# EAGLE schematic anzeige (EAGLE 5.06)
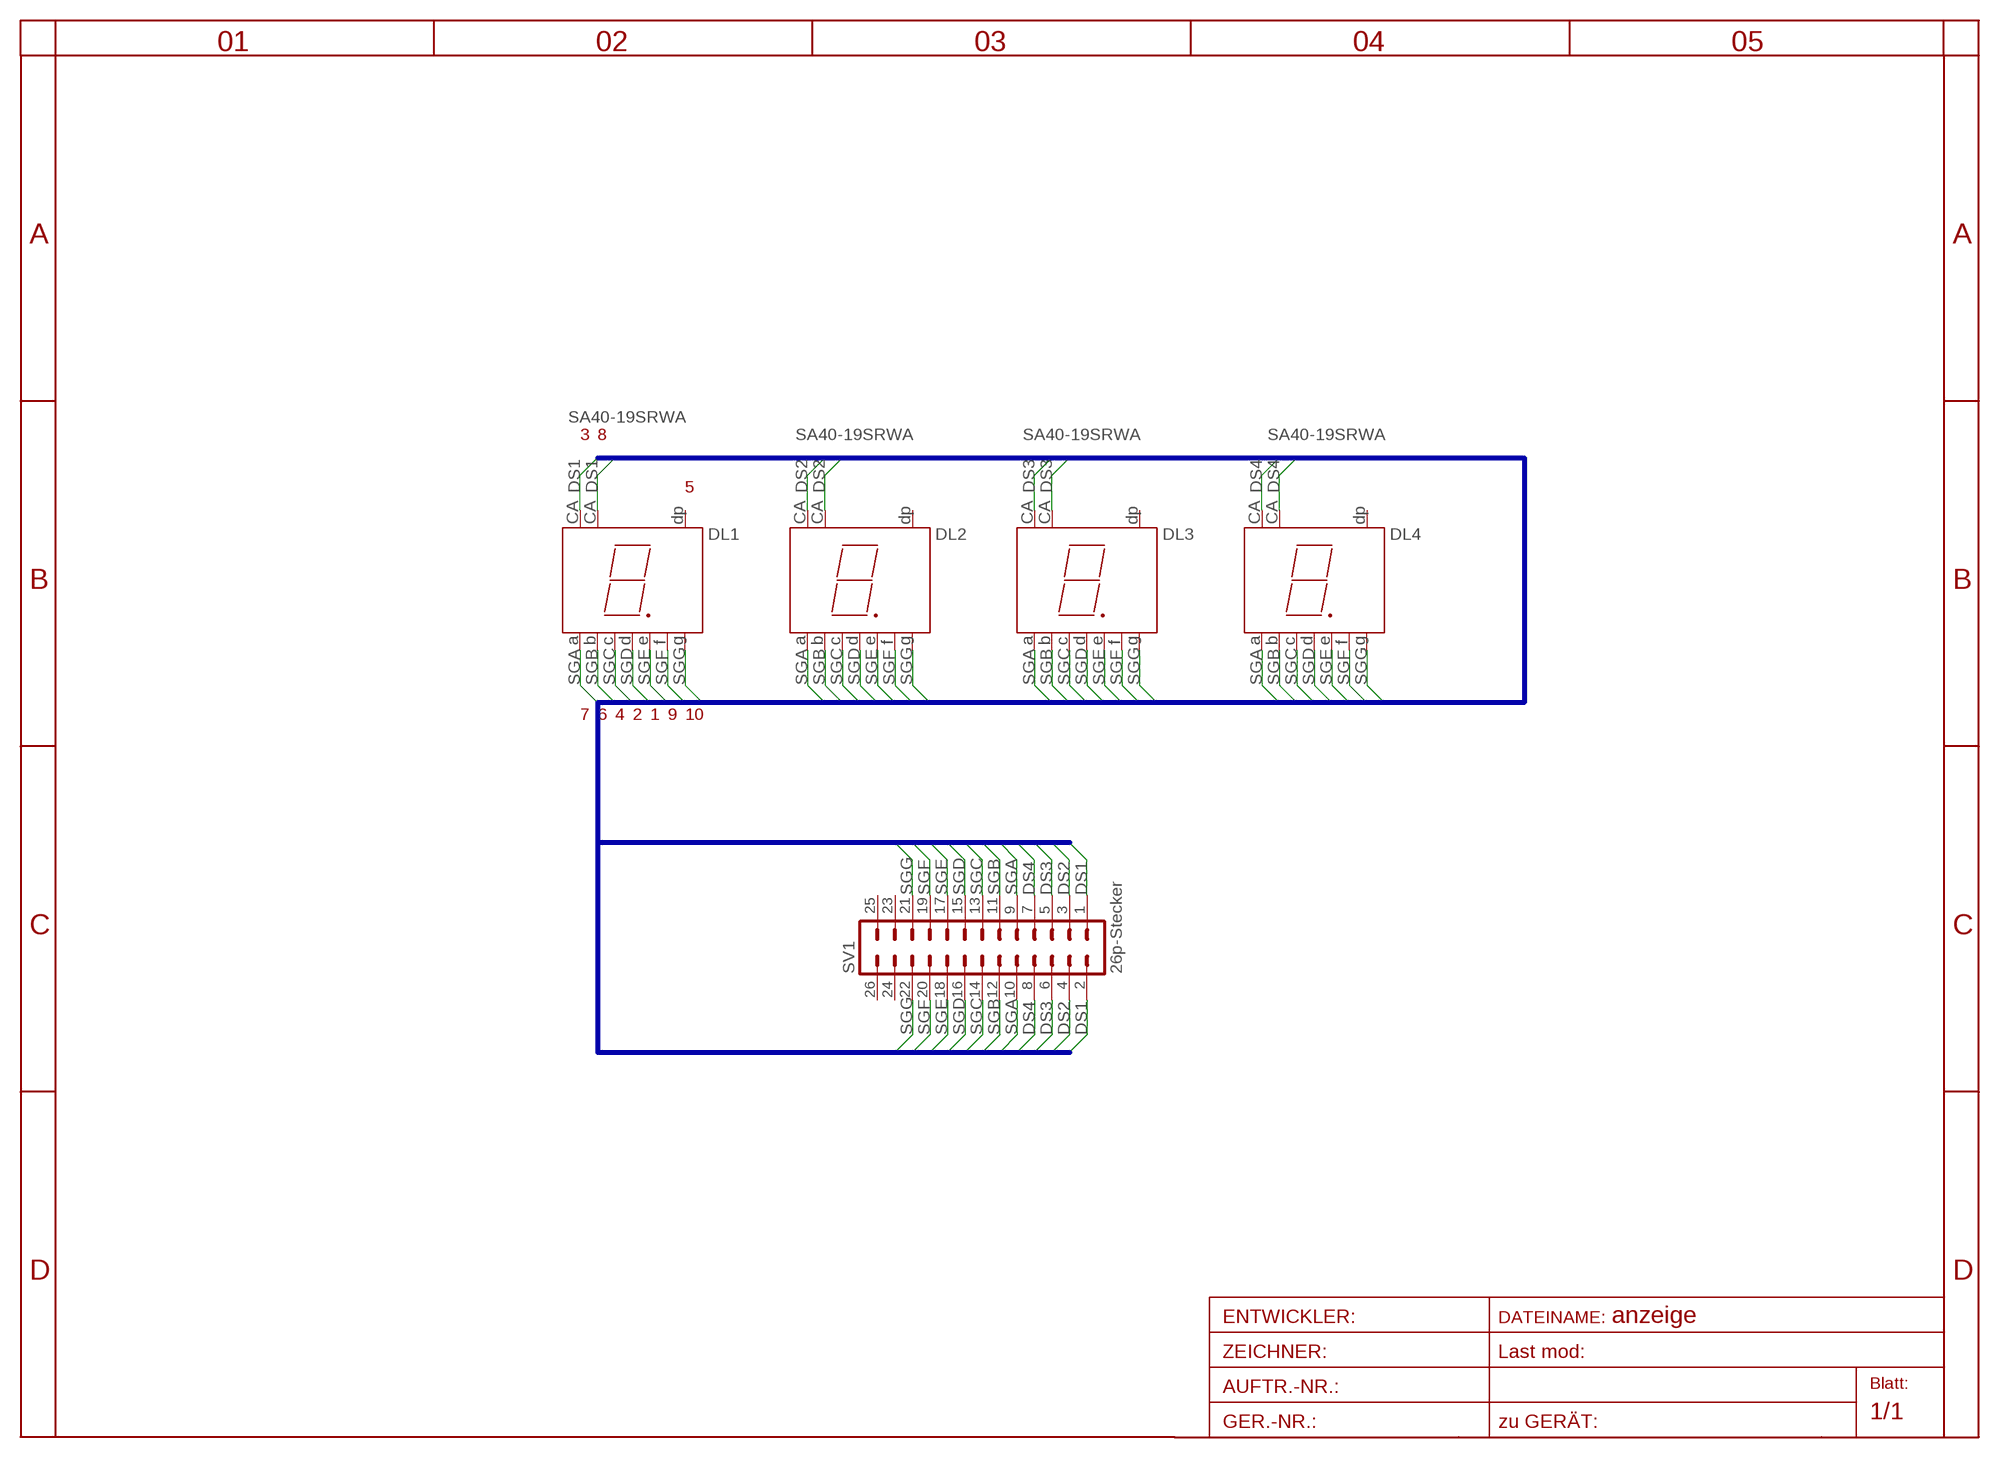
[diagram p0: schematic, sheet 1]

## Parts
DL1  SA40-19SRWA  SA18-11  [SA18-11]
DL2  SA40-19SRWA  SA18-11  [SA18-11]
DL3  SA40-19SRWA  SA18-11  [SA18-11]
DL4  SA40-19SRWA  SA18-11  [SA18-11]
SV1  26p-Stecker  ML263M  [3M_26]

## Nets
DS1: DL1.1(CA) DL1.5(CA) SV1.1 SV1.2
DS2: DL2.1(CA) DL2.5(CA) SV1.3 SV1.4
DS3: DL3.1(CA) DL3.5(CA) SV1.5 SV1.6
DS4: DL4.1(CA) DL4.5(CA) SV1.7 SV1.8
SGA: DL1.7(A) DL2.7(A) DL3.7(A) DL4.7(A) SV1.9 SV1.10
SGB: DL1.6(B) DL2.6(B) DL3.6(B) DL4.6(B) SV1.11 SV1.12
SGC: DL1.4(C) DL2.4(C) DL3.4(C) DL4.4(C) SV1.13 SV1.14
SGD: DL1.3(D) DL2.3(D) DL3.3(D) DL4.3(D) SV1.15 SV1.16
SGE: DL1.2(E) DL2.2(E) DL3.2(E) DL4.2(E) SV1.17 SV1.18
SGF: DL1.9(F) DL2.9(F) DL3.9(F) DL4.9(F) SV1.19 SV1.20
SGG: DL1.10(G) DL2.10(G) DL3.10(G) DL4.10(G) SV1.21 SV1.22
Unconnected: DL1.8(DP) DL2.8(DP) DL3.8(DP) DL4.8(DP) SV1.23 SV1.24 SV1.25 SV1.26

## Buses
BS:DS1,DS2,DS3,DS4,SGA,SGB,SGC,SGD,SGE,SGF,SGG

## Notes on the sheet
- 3 | 8
- 5
- 7 | 6 | 4 | 2 | 1 | 9 | 10

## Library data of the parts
DL1-DL4 = kingbright:SA18-11: Display 7 segmenti 56,9 mm anodo comune
SV1 = con-harting-ml:ML26: HARTING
